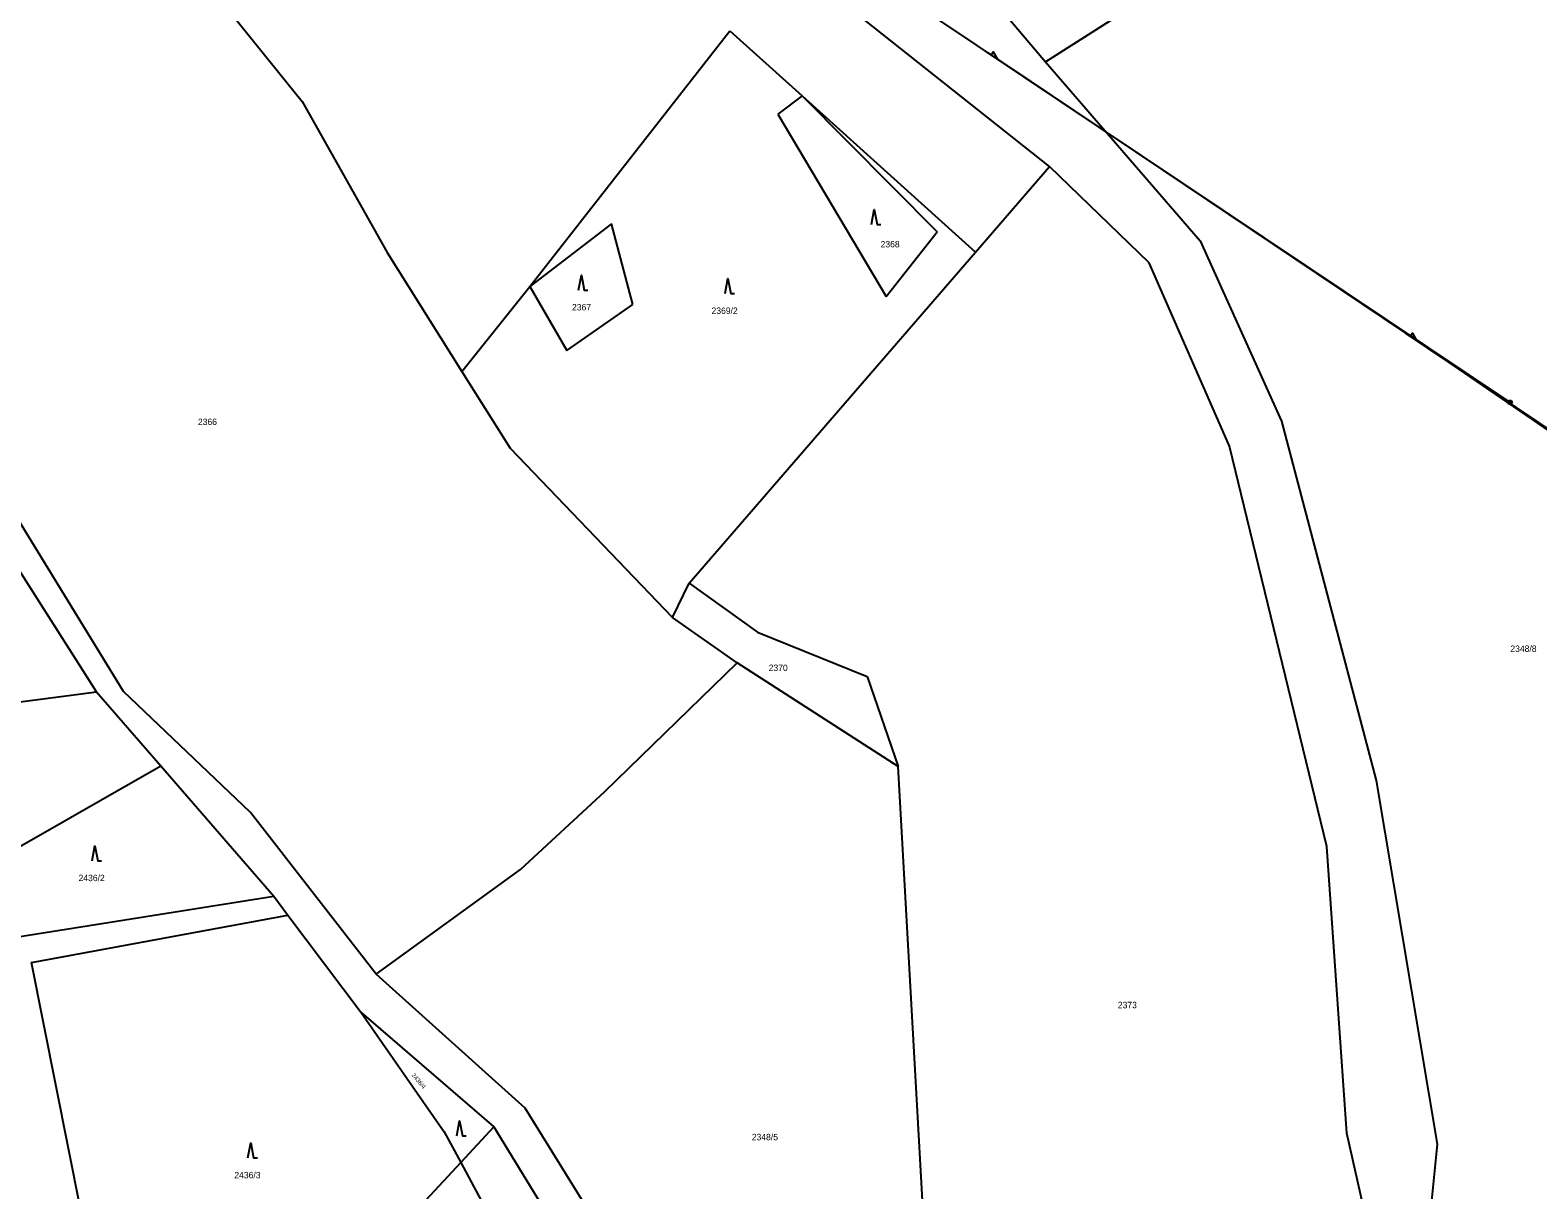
# Model space of a CAD drawing. Extents: x -747792 to -745414, y -1093712 to -1091463.
# Drawn here: x -746920.6 to -746720.5, y -1092850.4 to -1092696.5 of the extents above; entities that cross this region are included whole.
import ezdxf

# ---------------------------------------------------------------- set-up
doc = ezdxf.new("R2010")
doc.units = 0
for name, color, linetype in [('Budovy', 7, 'Continuous'), ('Koleje_dopravní prvky', 7, 'Continuous'), ('Stromy_porost', 7, 'Continuous'), ('Značky IS', 7, 'Continuous')]:
    doc.layers.add(name, color=color, linetype=linetype)

msp = doc.modelspace()

# ---------------------------------------------------------------- linework, layer by layer
at = {"layer": 'Budovy'}
for points in [[(-746808.95, -1092722.33), (-746808.57, -1092720.33), (-746808.2, -1092722.33), (-746807.7, -1092722.33)], [(-746847.8, -1092731.02), (-746847.42, -1092729.02), (-746847.05, -1092731.02), (-746846.55, -1092731.02)], [(-746828.35, -1092731.48), (-746827.98, -1092729.48), (-746827.6, -1092731.48), (-746827.1, -1092731.48)], [(-746912.33, -1092806.75), (-746911.96, -1092804.75), (-746911.58, -1092806.75), (-746911.08, -1092806.75)], [(-746863.96, -1092843.24), (-746863.59, -1092841.24), (-746863.21, -1092843.24), (-746862.71, -1092843.24)], [(-746891.66, -1092846.18), (-746891.28, -1092844.18), (-746890.91, -1092846.18), (-746890.41, -1092846.18)]]:
    msp.add_lwpolyline(points, dxfattribs=at)
at = {"layer": 'Stromy_porost'}
for points in [[(-746803.96, -1092679.3), (-746785.85, -1092700.75)], [(-746785.85, -1092700.75), (-746759.15, -1092683.68)], [(-746897.97, -1092689.22), (-746884.45, -1092706)], [(-746785.34, -1092714.62), (-746809.84, -1092695.18)], [(-746854.28, -1092730.55), (-746827.74, -1092696.63)], [(-746827.74, -1092696.63), (-746818.15, -1092705.26)], [(-746785.85, -1092700.75), (-746765.33, -1092724.48)], [(-746818.15, -1092705.26), (-746821.36, -1092707.67)], [(-746818.15, -1092705.26), (-746800.24, -1092723.28)], [(-746818.15, -1092705.26), (-746795.15, -1092725.97)], [(-746884.45, -1092706), (-746873.18, -1092726.05)], [(-746821.36, -1092707.67), (-746807.01, -1092731.87)], [(-746795.15, -1092725.97), (-746785.34, -1092714.62)], [(-746772.08, -1092727.42), (-746785.34, -1092714.62)], [(-746843.42, -1092722.22), (-746854.28, -1092730.55)], [(-746840.58, -1092732.95), (-746843.42, -1092722.22)], [(-746807.01, -1092731.87), (-746800.24, -1092723.28)], [(-746765.33, -1092724.48), (-746754.53, -1092748.43)], [(-746873.18, -1092726.05), (-746863.29, -1092741.8)], [(-746833.13, -1092769.9), (-746795.15, -1092725.97)], [(-746761.43, -1092751.74), (-746772.08, -1092727.42)], [(-746863.29, -1092741.8), (-746854.28, -1092730.55)], [(-746854.28, -1092730.55), (-746849.37, -1092739.04)], [(-746849.37, -1092739.04), (-746840.58, -1092732.95)], [(-746863.29, -1092741.8), (-746856.89, -1092751.99)], [(-746754.53, -1092748.43), (-746741.99, -1092796.08)], [(-746748.53, -1092804.87), (-746761.43, -1092751.74)], [(-746856.89, -1092751.99), (-746835.36, -1092774.48)], [(-746908.19, -1092784.29), (-746926.02, -1092755.16)], [(-746911.77, -1092784.31), (-746924.74, -1092763.95)], [(-746835.36, -1092774.48), (-746833.13, -1092769.9)], [(-746833.13, -1092769.9), (-746824.05, -1092776.4)], [(-746826.77, -1092780.46), (-746835.36, -1092774.48)], [(-746824.05, -1092776.4), (-746809.53, -1092782.31)], [(-746844.33, -1092797.56), (-746826.77, -1092780.46)], [(-746805.39, -1092794.22), (-746826.77, -1092780.46)], [(-746809.53, -1092782.31), (-746805.39, -1092794.22)], [(-746923.92, -1092785.91), (-746911.77, -1092784.31)], [(-746911.77, -1092784.31), (-746903.23, -1092794.16)], [(-746891.34, -1092800.35), (-746908.19, -1092784.29)], [(-746950.89, -1092821.39), (-746903.23, -1092794.16)], [(-746903.23, -1092794.16), (-746888.25, -1092811.43)], [(-746801.81, -1092858.13), (-746805.39, -1092794.22)], [(-746855.52, -1092807.91), (-746844.33, -1092797.56)], [(-746741.99, -1092796.08), (-746733.89, -1092844.34)], [(-746874.64, -1092821.78), (-746891.34, -1092800.35)], [(-746745.88, -1092842.91), (-746748.53, -1092804.87)], [(-746874.64, -1092821.78), (-746855.52, -1092807.91)], [(-746950.89, -1092821.39), (-746888.25, -1092811.43)], [(-746888.25, -1092811.43), (-746886.35, -1092813.96)], [(-746920.39, -1092820.23), (-746886.35, -1092813.96)], [(-746886.35, -1092813.96), (-746876.66, -1092826.89)], [(-746912.22, -1092861.18), (-746920.39, -1092820.23)], [(-746854.89, -1092839.59), (-746874.64, -1092821.78)], [(-746876.66, -1092826.89), (-746865.62, -1092842.71)], [(-746876.66, -1092826.89), (-746859.02, -1092842.05)], [(-746814.82, -1092904.3), (-746854.89, -1092839.59)], [(-746865.62, -1092842.71), (-746863.43, -1092846.8)], [(-746859.02, -1092842.05), (-746863.43, -1092846.8)], [(-746859.02, -1092842.05), (-746837.06, -1092878.01)], [(-746731.28, -1092907.69), (-746745.88, -1092842.91)], [(-746733.89, -1092844.34), (-746735.11, -1092856.73)], [(-746863.43, -1092846.8), (-746930.36, -1092918.77)], [(-746863.43, -1092846.8), (-746843.98, -1092883.18)]]:
    msp.add_lwpolyline(points, dxfattribs=at)
at = {"layer": 'Značky IS'}
for points in [[(-746860.24, -1092654.82), (-746724.22, -1092745.92), (-746793.68, -1092699.4)], [(-746793.48, -1092699.54), (-746793.06, -1092699.82), (-746792.78, -1092699.4), (-746792.23, -1092700.37), (-746790.98, -1092701.21)], [(-746790.78, -1092701.35), (-746682.46, -1092774.09), (-746738.07, -1092736.74)], [(-746737.86, -1092736.88), (-746737.45, -1092737.16), (-746737.17, -1092736.75), (-746736.62, -1092737.72), (-746735.37, -1092738.55)], [(-746735.17, -1092738.69), (-746640.77, -1092803.34), (-746689.41, -1092770.03)], [(-746724.29, -1092745.68), (-746724.14, -1092745.68), (-746724.01, -1092745.77), (-746723.96, -1092745.92), (-746724.01, -1092746.06), (-746724.14, -1092746.15), (-746724.29, -1092746.15), (-746724.42, -1092746.06), (-746724.47, -1092745.92), (-746724.42, -1092745.77), (-746724.29, -1092745.68), (-746724.28, -1092745.7), (-746724.16, -1092745.7), (-746724.08, -1092745.74), (-746724.36, -1092745.74), (-746724.4, -1092745.78), (-746724.04, -1092745.78), (-746724.04, -1092745.82), (-746724.4, -1092745.82), (-746724.42, -1092745.86), (-746724.02, -1092745.86), (-746724, -1092745.9), (-746724.44, -1092745.9), (-746724.44, -1092745.94), (-746724, -1092745.94), (-746724.01, -1092745.98), (-746724.42, -1092745.98), (-746724.42, -1092746.02), (-746724.01, -1092746.02), (-746724.03, -1092746.06), (-746724.4, -1092746.06), (-746724.35, -1092746.1), (-746724.08, -1092746.1), (-746724.13, -1092746.14), (-746724.3, -1092746.14)]]:
    msp.add_lwpolyline(points, dxfattribs=at)

# ---------------------------------------------------------------- texts
at = {"layer": 'Koleje_dopravní prvky'}
for s, p in [('2368', (-746807.73, -1092725.35)), ('2367', (-746848.67, -1092733.72)), ('2369/2', (-746830.16, -1092734.18)), ('2366', (-746898.3, -1092748.93)), ('2348/8', (-746724.18, -1092779.03)), ('2370', (-746822.58, -1092781.56)), ('2436/2', (-746914.14, -1092809.45)), ('2373', (-746776.26, -1092826.31)), ('2348/5', (-746824.82, -1092843.83)), ('2436/3', (-746893.47, -1092848.88))]:
    msp.add_text(s, height=0.85, dxfattribs=at).set_placement(p)
msp.add_text('2436/4', height=0.57, rotation=310.3139, dxfattribs=at).set_placement((-746869.99, -1092835.22))

doc.saveas('drawing.dxf')
